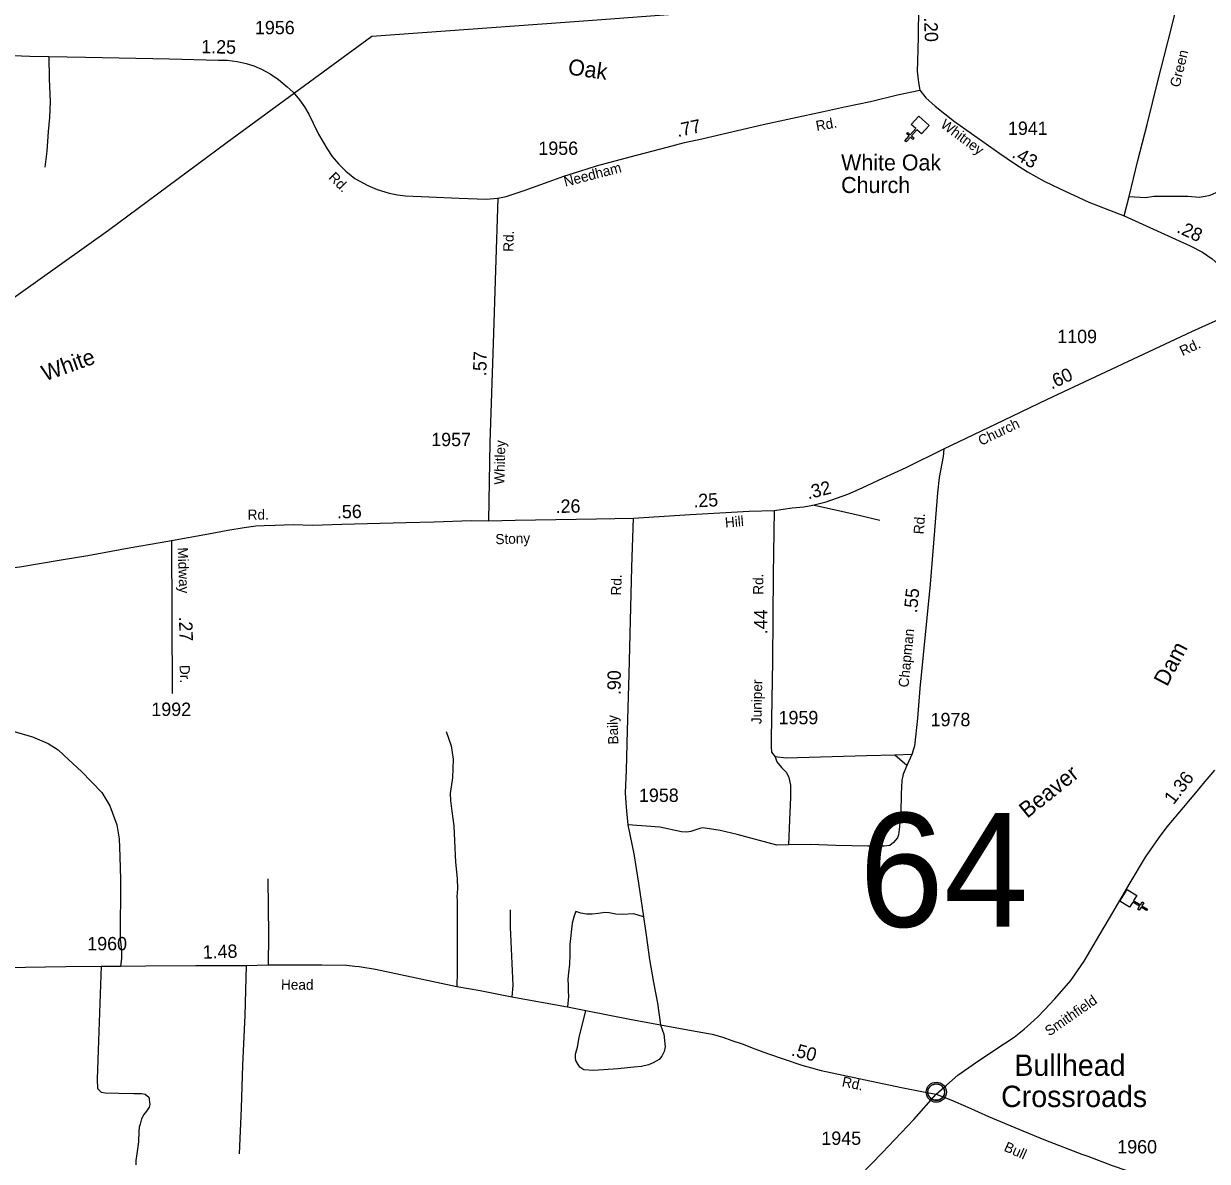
# Model space of a CAD drawing. Extents: x 2220236 to 2384410, y 720751 to 894131.
# Drawn here: x 2269607 to 2280691, y 744247 to 754902 of the extents above; entities that cross this region are included whole.
import ezdxf

# ---------------------------------------------------------------- set-up
doc = ezdxf.new("R2010")
doc.units = 0
doc.layers.add('Default', color=7, linetype='Continuous')

msp = doc.modelspace()

# ---------------------------------------------------------------- linework, layer by layer
at = {"layer": 'Default'}
for p, q in [((2270990, 750061), (2270997, 748629)), ((2277923, 748058), (2277765, 748050)), ((2277923, 748058), (2277876, 747955)), ((2277876, 747955), (2277765, 748050))]:
    msp.add_line(p, q, dxfattribs=at)
for points in [[(2296526, 756314), (2294600, 756208), (2292309, 756063), (2290035, 755921), (2287749, 755780), (2285466, 755635), (2283160, 755491), (2281790, 755396), (2279029, 755228), (2276729, 755065), (2274892, 754928), (2272866, 754783), (2271512, 753789), (2270402, 752966), (2269282, 752170), (2268166, 751348), (2267047, 750534), (2265929, 749726), (2264444, 748641), (2263328, 747822), (2262406, 747872), (2261484, 747927), (2260116, 748002), (2259542, 748037)], [(2277988, 755346), (2277982, 754779), (2277976, 754548), (2277974, 754457), (2277986, 754351), (2277998, 754280)], [(2279912, 753102), (2279960, 753282), (2280041, 753620), (2280128, 753956), (2280231, 754375), (2280287, 754593), (2280362, 754887), (2280416, 755105)], [(2269435, 754606), (2269666, 754598), (2269844, 754595), (2270187, 754589), (2270974, 754572), (2271433, 754561), (2271513, 754559), (2271606, 754548), (2271691, 754530), (2271761, 754507), (2271834, 754476), (2271914, 754432), (2271993, 754380), (2272075, 754311), (2272130, 754259), (2272189, 754189), (2272238, 754122), (2272277, 754055), (2272319, 753970), (2272369, 753866), (2272449, 753729), (2272495, 753659), (2272554, 753589), (2272625, 753520), (2272707, 753453), (2272829, 753386), (2272917, 753349), (2273029, 753315), (2273107, 753298), (2273184, 753290), (2273402, 753280), (2273686, 753267), (2273938, 753258), (2274047, 753267)], [(2269844, 754595), (2269847, 754385), (2269855, 754169), (2269850, 754022), (2269836, 753892), (2269823, 753707), (2269806, 753558)], [(2274047, 753267), (2274124, 753284), (2274295, 753338), (2274529, 753424), (2274666, 753474), (2274814, 753522), (2274971, 753571), (2275287, 753655), (2275632, 753745), (2275796, 753789), (2275956, 753823), (2276531, 753958), (2276808, 754016), (2277096, 754078), (2277295, 754123), (2277536, 754174), (2277790, 754234), (2277998, 754280)], [(2277998, 754280), (2278055, 754206), (2278141, 754130), (2278323, 753985), (2278748, 753687), (2278884, 753591), (2279007, 753515), (2279162, 753428), (2279307, 753359), (2279580, 753231), (2279912, 753102)], [(2279960, 753282), (2280113, 753275), (2280189, 753286), (2280510, 753285), (2280616, 753276), (2280670, 753285), (2280718, 753295), (2280774, 753320), (2280824, 753358), (2280879, 753433), (2280954, 753547)], [(2274047, 753267), (2274024, 752592), (2274004, 751906), (2273972, 750980), (2273960, 750245)], [(2279912, 753102), (2280529, 752822), (2280647, 752763), (2280736, 752699), (2280788, 752652), (2280842, 752575), (2280945, 752462), (2281085, 752263)], [(2278224, 750919), (2278785, 751188), (2279193, 751386), (2280546, 752020), (2281085, 752263)], [(2276634, 750342), (2276802, 750366), (2276913, 750378), (2276998, 750393), (2277122, 750424), (2277325, 750496), (2277458, 750556), (2277653, 750646), (2277870, 750744), (2278224, 750919)], [(2278224, 750919), (2278216, 750847), (2278180, 750651), (2278164, 750509), (2278124, 749998), (2278096, 749652), (2277999, 748676), (2277976, 748396), (2277948, 748136), (2277938, 748098), (2277923, 748058)], [(2277623, 750250), (2277443, 750291), (2277238, 750340), (2276998, 750393)], [(2273960, 750245), (2274211, 750251), (2274971, 750263), (2275314, 750272)], [(2275314, 750272), (2275300, 749812), (2275274, 748810), (2275257, 748282), (2275250, 747909), (2275240, 747697), (2275245, 747605), (2275252, 747528), (2275264, 747398), (2275321, 747128), (2275364, 746851), (2275410, 746536), (2275436, 746364), (2275469, 746136), (2275506, 745921), (2275541, 745728), (2275572, 745526)], [(2275314, 750272), (2275849, 750306), (2276125, 750320), (2276400, 750335), (2276634, 750342)], [(2276634, 750342), (2276626, 749742), (2276618, 748935), (2276608, 748207), (2276606, 748128), (2276611, 748080), (2276644, 748036)], [(2270990, 750061), (2271337, 750124), (2271519, 750157), (2271671, 750182), (2271781, 750198), (2271858, 750203), (2271963, 750206), (2272130, 750211), (2272314, 750206), (2272587, 750214), (2273186, 750230), (2273451, 750237), (2273798, 750248), (2273960, 750245)], [(2266988, 749779), (2267326, 749777), (2267483, 749774), (2267655, 749774), (2267833, 749776), (2268482, 749766), (2269143, 749779), (2269321, 749785), (2269570, 749816), (2269755, 749846), (2269959, 749879), (2270209, 749920), (2270595, 749993), (2270886, 750042), (2270990, 750061)], [(2269320, 748357), (2269384, 748325), (2269517, 748273), (2269689, 748224), (2269838, 748160), (2269930, 748102), (2270031, 748007), (2270150, 747899), (2270338, 747701), (2270413, 747575), (2270481, 747398), (2270502, 747266), (2270509, 747101), (2270515, 746885), (2270511, 746325), (2270522, 746227), (2270522, 746147), (2270515, 746073)], [(2273564, 748271), (2273610, 748137), (2273630, 748014), (2273624, 747838), (2273602, 747693), (2273605, 747625), (2273616, 747527), (2273635, 747388), (2273641, 747248), (2273652, 747050), (2273668, 746896), (2273669, 746800), (2273663, 746723), (2273665, 746693), (2273665, 746657), (2273665, 746598), (2273665, 746444), (2273665, 746281), (2273667, 746136), (2273667, 746022), (2273664, 745883)], [(2277765, 748050), (2277501, 748046), (2276747, 748023), (2276644, 748036)], [(2276644, 748036), (2276660, 747988), (2276702, 747934), (2276751, 747889), (2276771, 747843), (2276788, 747769), (2276789, 747657), (2276779, 747443), (2276769, 747211)], [(2277876, 747955), (2277844, 747873), (2277831, 747815), (2277824, 747689), (2277820, 747511), (2277805, 747353), (2277798, 747305), (2277789, 747276), (2277770, 747255), (2277752, 747232), (2277717, 747205), (2277666, 747199), (2277512, 747199), (2277213, 747206), (2276975, 747213), (2276769, 747211)], [(2278152, 744877), (2278248, 744961), (2278354, 745053), (2278520, 745170), (2278720, 745302), (2278881, 745411), (2278976, 745485), (2279036, 745537), (2279105, 745600), (2279167, 745664), (2279263, 745768), (2279412, 745941), (2279538, 746120), (2279685, 746371), (2279817, 746592), (2279960, 746839), (2280112, 747094), (2280233, 747269), (2280315, 747379), (2280468, 747560), (2280600, 747717), (2280656, 747785), (2280762, 747909)], [(2276769, 747211), (2276661, 747209), (2276287, 747309), (2276128, 747345), (2275990, 747367), (2275962, 747369), (2275938, 747365), (2275853, 747335), (2275818, 747331), (2275768, 747333), (2275565, 747376), (2275264, 747398)], [(2271895, 746892), (2271900, 746364), (2271896, 746086)], [(2274162, 746601), (2274162, 746437), (2274169, 746305), (2274187, 745894), (2274179, 745787)], [(2275410, 746536), (2275320, 746564), (2275210, 746559), (2275152, 746560), (2275090, 746574), (2275050, 746577), (2274990, 746567), (2274932, 746562), (2274876, 746562), (2274824, 746571), (2274778, 746585), (2274762, 746545), (2274743, 746477), (2274721, 746276), (2274722, 746181), (2274717, 746092), (2274708, 746012), (2274704, 745953), (2274707, 745893), (2274705, 745841), (2274710, 745791), (2274701, 745695)], [(2267810, 746072), (2268106, 746057), (2268361, 746043), (2268710, 746040), (2269054, 746055), (2270001, 746070), (2270333, 746073), (2270515, 746073), (2270751, 746077), (2271220, 746082), (2271692, 746080), (2271896, 746086), (2272400, 746087), (2272630, 746085), (2272708, 746076), (2272750, 746072), (2272902, 746045), (2273664, 745883), (2273882, 745847), (2274179, 745787), (2274701, 745695), (2274872, 745658), (2275283, 745579), (2275572, 745526)], [(2270333, 746073), (2270306, 745289), (2270295, 745015), (2270299, 744929), (2270334, 744893), (2270374, 744888), (2270495, 744886), (2270640, 744883), (2270709, 744882), (2270746, 744877), (2270780, 744848), (2270787, 744780), (2270781, 744754), (2270756, 744716), (2270732, 744686), (2270712, 744644), (2270697, 744595), (2270690, 744566), (2270687, 744526), (2270681, 744428), (2270667, 744316), (2270658, 744253), (2270658, 744213)], [(2271692, 746080), (2271679, 745614), (2271657, 745146), (2271643, 744746), (2271625, 744316)], [(2275572, 745526), (2275602, 745439), (2275609, 745379), (2275614, 745319), (2275606, 745275), (2275584, 745233), (2275559, 745201), (2275503, 745168), (2275457, 745150), (2275393, 745135), (2275320, 745127), (2275174, 745113), (2274942, 745098), (2274854, 745104), (2274816, 745130), (2274800, 745154), (2274777, 745190), (2274776, 745214), (2274775, 745249), (2274794, 745315), (2274808, 745405), (2274872, 745658)], [(2275572, 745526), (2275825, 745478), (2276053, 745437), (2276155, 745409), (2276240, 745379), (2276344, 745343), (2276430, 745309), (2276571, 745255), (2276728, 745202), (2276894, 745146), (2277076, 745098), (2277486, 745010), (2277828, 744939), (2278049, 744893), (2278152, 744877)], [(2275299, 741868), (2275403, 741953), (2275447, 742001), (2275565, 742143), (2275867, 742449), (2276136, 742722), (2276435, 743042), (2276774, 743401), (2277442, 744116), (2277645, 744327), (2277943, 744638), (2278152, 744877)], [(2278152, 744877), (2278290, 744824), (2278448, 744754), (2278641, 744668), (2278963, 744531), (2279176, 744445), (2279517, 744314), (2279573, 744294), (2279800, 744207), (2280066, 744117), (2280411, 744037), (2280670, 743988), (2281988, 743730)]]:
    msp.add_lwpolyline(points, dxfattribs=at)
for points in [[(2278015, 753870), (2277972, 753908), (2277921, 753851), (2277945, 753830), (2277934, 753818), (2277911, 753839), (2277870, 753795), (2277858, 753806), (2277899, 753850), (2277875, 753872), (2277886, 753884), (2277909, 753862), (2277960, 753919), (2277918, 753957), (2277989, 754036), (2278086, 753949)], [(2280030, 746737), (2280000, 746689), (2280065, 746649), (2280082, 746676), (2280095, 746668), (2280079, 746640), (2280130, 746609), (2280121, 746595), (2280070, 746627), (2280053, 746599), (2280040, 746608), (2280057, 746635), (2279992, 746675), (2279961, 746626), (2279871, 746682), (2279940, 746793)], [(2278075, 744907), (2278076, 744912), (2278078, 744919), (2278081, 744926), (2278084, 744932), (2278087, 744938), (2278091, 744943), (2278095, 744947), (2278099, 744952), (2278105, 744956), (2278110, 744960), (2278115, 744963), (2278120, 744965), (2278126, 744967), (2278131, 744969), (2278136, 744970), (2278140, 744971), (2278145, 744972), (2278151, 744972), (2278155, 744972), (2278161, 744972), (2278166, 744971), (2278171, 744970), (2278176, 744969), (2278181, 744967), (2278188, 744964), (2278194, 744960), (2278199, 744957), (2278204, 744953), (2278207, 744950), (2278212, 744945), (2278215, 744941), (2278218, 744936), (2278222, 744931), (2278224, 744926), (2278226, 744921), (2278228, 744916), (2278229, 744911), (2278230, 744905), (2278231, 744900), (2278231, 744894), (2278231, 744889), (2278230, 744883), (2278229, 744877), (2278228, 744871), (2278226, 744865), (2278223, 744860), (2278220, 744854), (2278217, 744849), (2278214, 744844), (2278209, 744840), (2278204, 744835), (2278199, 744831), (2278194, 744827), (2278190, 744825), (2278183, 744821), (2278176, 744819), (2278170, 744817), (2278163, 744816), (2278159, 744815), (2278154, 744815), (2278149, 744815), (2278144, 744816), (2278139, 744816), (2278133, 744818), (2278128, 744819), (2278123, 744821), (2278118, 744823), (2278115, 744825), (2278108, 744829), (2278102, 744833), (2278097, 744838), (2278093, 744843), (2278090, 744847), (2278087, 744851), (2278083, 744858), (2278081, 744862), (2278079, 744866), (2278077, 744874), (2278075, 744881), (2278074, 744886), (2278074, 744892), (2278074, 744897), (2278074, 744903)]]:
    msp.add_lwpolyline(points, close=True, dxfattribs=at)
for centre, radius in [((2278153, 744894), 94.3), ((2278152, 744895), 76.7)]:
    msp.add_circle(centre, radius, dxfattribs=at)

# ---------------------------------------------------------------- texts
for s, height, p in [('1956', 125, (2271773, 754803)), ('1941', 125, (2278824, 753860)), ('1956', 125, (2274427, 753673)), ('White Oak', 150, (2277262, 753527)), ('Church', 150, (2277262, 753316)), ('1109', 125, (2279286, 751910)), ('1957', 125, (2273424, 750945)), ('1992', 125, (2270803, 748418)), ('1959', 125, (2276676, 748340)), ('1978', 125, (2278100, 748322)), ('1958', 125, (2275369, 747613)), ('64', 1066.3, (2277431, 746443)), ('1960', 125, (2270203, 746223)), ('Bullhead', 200, (2278884, 745047)), ('Crossroads', 200, (2278760, 744755)), ('1945', 125, (2277077, 744401)), ('1960', 125, (2279848, 744321))]:
    msp.add_text(s, height=height, dxfattribs=at).set_placement(p)
for s, height, rotation, p in [('.20', 125, 272.1252, (2278038, 754961)), ('1.25', 125, 358.8306, (2271269, 754626)), ('Green', 95, 76.404, (2280431, 754300)), ('Oak', 150, 351.9584, (2274698, 754427)), ('.77', 125, 12.1024, (2275732, 753839)), ('Rd.', 95, 10.2275, (2277034, 753896)), ('Whitney', 95, 323.5406, (2278185, 753939)), ('.43', 125, 330.9297, (2278853, 753654)), ('Rd.', 95, 314.9927, (2272456, 753455)), ('Needham', 95, 14.5639, (2274679, 753374)), ('Rd.', 95, 88.3599, (2274192, 752764)), ('.28', 125, 335.5596, (2280397, 752950)), ('Rd.', 95, 25.1143, (2280459, 751787)), ('White', 150, 19.601, (2269807, 751551)), ('.57', 125, 88.0368, (2273938, 751600)), ('.60', 125, 25.1143, (2279233, 751474)), ('Church', 95, 25.6141, (2278573, 750947)), ('Whitley', 95, 88.5399, (2274108, 750583)), ('.32', 125, 14.1758, (2276953, 750446)), ('.25', 125, 2.9889, (2275881, 750370)), ('.56', 125, 1.3907, (2272542, 750267)), ('.26', 125, 0.8474, (2274589, 750319)), ('Rd.', 95, 0.6103, (2271705, 750255)), ('Hill', 95, 4.9574, (2276178, 750182)), ('Rd.', 95, 85.6065, (2278034, 750117)), ('Stony', 95, 1.7902, (2274026, 750026)), ('Midway', 95, 272.0671, (2271049, 749995)), ('Rd.', 95, 88.0123, (2275201, 749545)), ('Rd.', 95, 89.3607, (2276532, 749553)), ('.55', 125, 84.2212, (2277972, 749378)), ('.44', 125, 89.3607, (2276570, 749183)), ('.27', 125, 272.0671, (2271060, 749347)), ('Chapman', 95, 84.35, (2277892, 748682)), ('Dam', 150, 62.2256, (2280314, 748686)), ('Dr.', 95, 272.0671, (2271067, 748894)), ('.90', 125, 89.3255, (2275197, 748613)), ('Juniper', 95, 89.0093, (2276516, 748341)), ('Baily', 95, 91.7375, (2275176, 748152)), ('Beaver', 150, 38.7086, (2279004, 747454)), ('1.36', 125, 52.6267, (2280375, 747580)), ('1.48', 125, 1.6856, (2271285, 746144)), ('Head', 95, 359.5765, (2272017, 745855)), ('Smithfield', 95, 34.8017, (2279211, 745415)), ('.50', 125, 345.1384, (2276788, 745239)), ('Rd.', 95, 348.4366, (2277264, 744949)), ('Bull', 95, 335.8957, (2278779, 744348))]:
    msp.add_text(s, height=height, rotation=rotation, dxfattribs=at).set_placement(p)

doc.saveas('drawing.dxf')
